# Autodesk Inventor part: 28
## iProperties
Created: 2011-11
Part Number: 28
Document SubType Name: Modeling
Designer: D Cole
Density: 1 g/cm^3
Translation Standard: STEP AP214IS
File Name: P:\Fastrack\53972_CRANE 3D\Press Fit\HATTERSLEY\100-TH\28MM\28.stp
Preprocessor: Autodesk Inventor 2008
Postprocessor: Build: 342, Release: 2008 SP3 - Date: Tue 05/27/2008
Sent Units: MILLIMETERS
Uncertainty: 0.01
Author: D Cole
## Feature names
1. Base1
